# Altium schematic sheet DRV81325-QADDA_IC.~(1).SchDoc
size 431 x 279 mm; Date: Not shown in title block; ApprovedBy: Not shown in title block; CheckedBy: Not shown in title block; Author: Not shown in title block; CompanyName: Not shown in title block; Engineer: Not shown in title block; Organization: Not shown in title block; Address1: Not shown in title block; Address2: Not shown in title block; Address3: Not shown in title block; Address4: Not shown in title block; DocumentNumber: 1; Revision: Use project parameter SCH_Rev; SheetNumber: 4; SheetTotal: 5; PageSetup: Record=PageOptions¦CenterHorizontal=True¦CenterVertical=True¦PrintScale=1.00¦XCorrection=1.00¦YCorrection=1.00¦PrintKind=0¦BorderSize=5000000¦LeftOffset=0¦BottomOffset=0¦Orientation=2¦PaperLength=1000¦PaperWidth=1000¦Scale=100¦PaperSource=15¦PrintQuality=600¦MediaType=1¦DitherType=10¦PaperKind=Letter¦PrintScaleMode=1
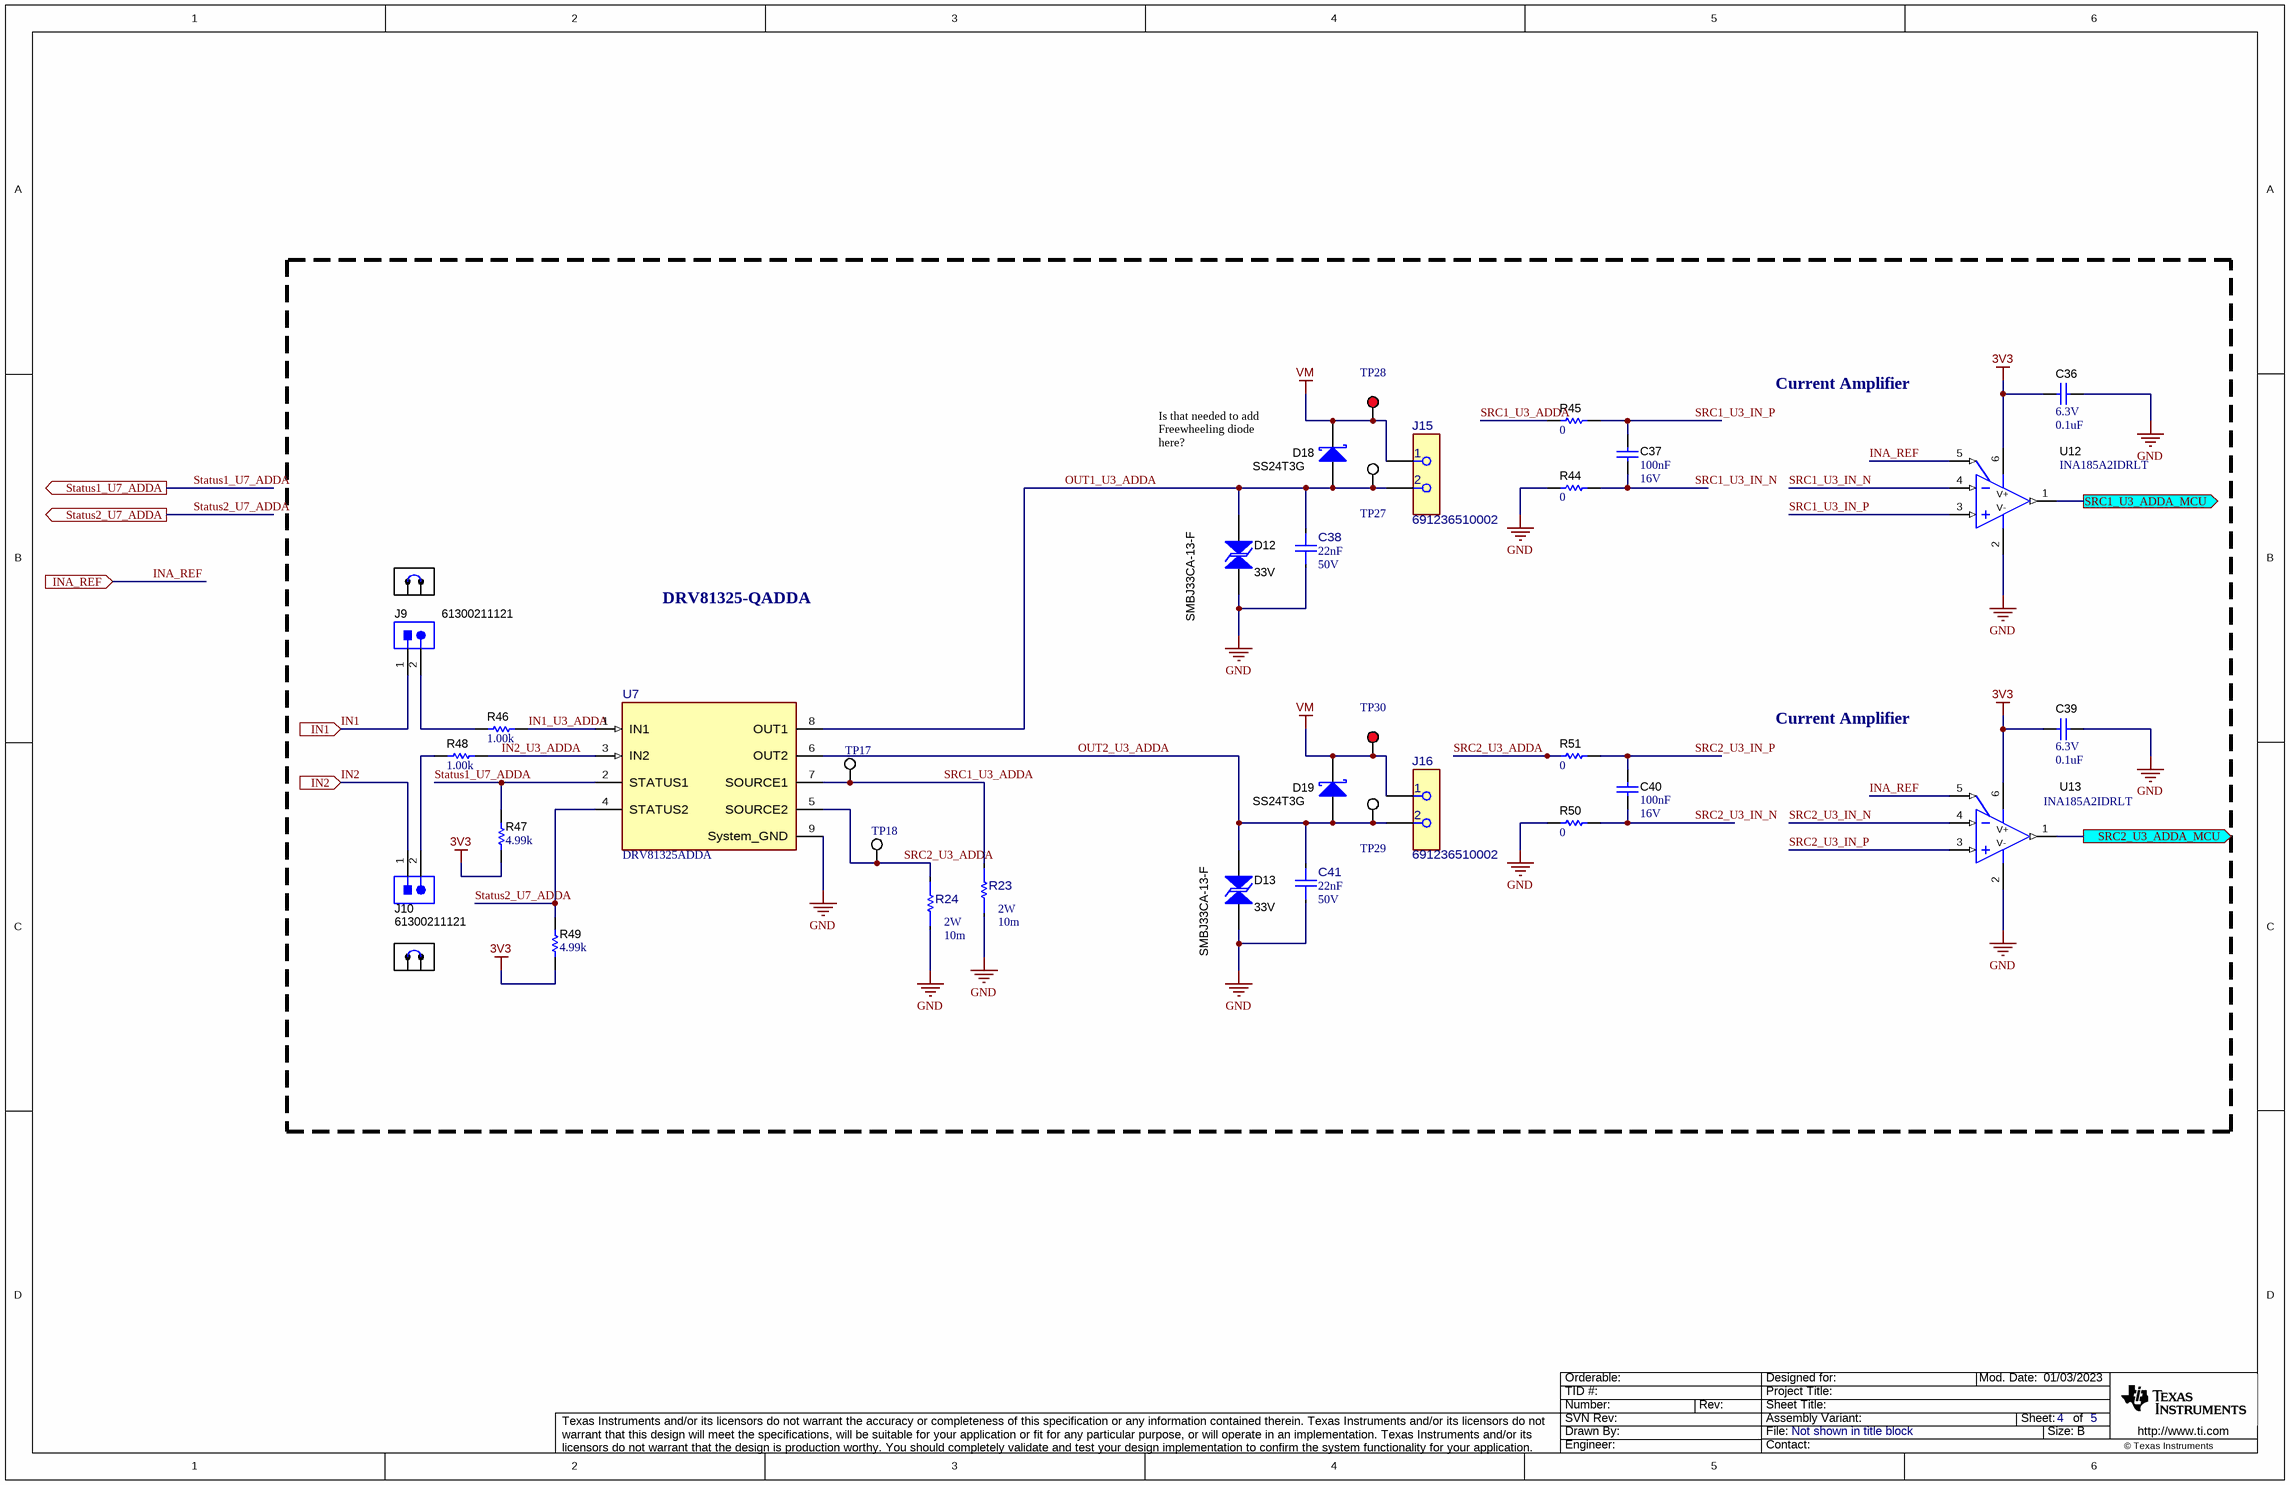
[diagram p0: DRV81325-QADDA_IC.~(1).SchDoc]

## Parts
C36  VDC_V: 6.3V  ValueDisplayed: 0.1uF  [0402]  (hidden comment: 885012105001)
C37  Cap_F: 100nF  VDC_V: 16V  [0603]  (hidden comment: 885012206046)
C38  Cap_F: 22nF  VDC_V: 50V  [FP-885012206091_0603-MFG]  (hidden comment: 885012206091)
C39  VDC_V: 6.3V  ValueDisplayed: 0.1uF  [0402]  (hidden comment: 885012105001)
C40  Cap_F: 100nF  VDC_V: 16V  [0603]  (hidden comment: 885012206046)
C41  Cap_F: 22nF  VDC_V: 50V  [FP-885012206091_0603-MFG]  (hidden comment: 885012206091)
D12  SMBJ33CA-13-F  value 33V  [SMB-Bi]
D13  SMBJ33CA-13-F  value 33V  [SMB-Bi]
D18  SS24T3G  [SMB]
D19  SS24T3G  [SMB]
J9  61300211121  [WURTH_61300211121]
J10  61300211121  [WURTH_61300211121]
J15  691236510002  [FP-691236510002_HHR2-MFG]
J16  691236510002  [FP-691236510002_HHR2-MFG]
R23  Res_ohm: 10m  Power_W: 2W  [FP-PCS2512DR0100ET_2512-MFG]  (hidden comment: PCS2512DR0100ET)
R24  Res_ohm: 10m  Power_W: 2W  [FP-PCS2512DR0100ET_2512-MFG]  (hidden comment: PCS2512DR0100ET)
R44  ValueDisplayed: 0  [0603]  (hidden comment: ERJ-3GEY0R00V)
R45  ValueDisplayed: 0  [0603]  (hidden comment: ERJ-3GEY0R00V)
R46  ValueDisplayed: 1.00k  [0603]  (hidden comment: RC0603FR-071KL)
R47  ValueDisplayed: 4.99k  [0603]  (hidden comment: RC0603FR-074K99L)
R48  ValueDisplayed: 1.00k  [0603]  (hidden comment: RC0603FR-071KL)
R49  ValueDisplayed: 4.99k  [0603]  (hidden comment: RC0603FR-074K99L)
R50  ValueDisplayed: 0  [0603]  (hidden comment: ERJ-3GEY0R00V)
R51  ValueDisplayed: 0  [0603]  (hidden comment: ERJ-3GEY0R00V)
SH-J9  60900213421  [Wurth_60900213421]  (value not drawn)
SH-J10  60900213421  [Wurth_60900213421]  (value not drawn)
TP17  5002  [Keystone5002]  (value not drawn)
TP18  5002  [Keystone5002]  (value not drawn)
TP27  5012  [Keystone5012]  (value not drawn)
TP28  5010  [Keystone5010]  (value not drawn)
TP29  5012  [Keystone5012]  (value not drawn)
TP30  5010  [Keystone5010]  (value not drawn)
U7  DRV81325ADDA  [DDA0008B-MFG]
U12  INA185A2IDRLT  [DRL0006A]
U13  INA185A2IDRLT  [DRL0006A]

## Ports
IN1 (in), IN2 (in), INA_REF (in), SRC1_U3_ADDA_MCU (out), SRC2_U3_ADDA_MCU (out), Status1_U7_ADDA (out), Status2_U7_ADDA (out)

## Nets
3V3: C36.2 C39.2 R47.1 R49.1 U12.6(V+) U13.6(V+)
GND: C36.1 C38.1 C39.1 C41.1 D12.1 D13.1 R23.1 R24.1 R44.1 R50.1 U7.9(System_GND) U12.2(V-) U13.2(V-)
VM: D18.1(K) D19.1(K) J15.1 J16.1 TP28.1 TP30.1
IN1: J9.1 ; port IN1
IN1_U3_ADDA: R46.2 U7.1(IN1)
IN2: J10.1 ; port IN2
IN2_U3_ADDA: R48.2 U7.3(IN2)
INA_REF: U12.5(REF) U13.5(REF) ; port INA_REF
OUT1_U3_ADDA: C38.2 D12.2 D18.2(A) J15.2 TP27.1 U7.8(OUT1)
OUT2_U3_ADDA: C41.2 D13.2 D19.2(A) J16.2 TP29.1 U7.6(OUT2)
SRC1_U3_ADDA: R23.2 R45.1 TP17.1 U7.7(SOURCE1)
SRC1_U3_ADDA_MCU: U12.1(OUT) ; port SRC1_U3_ADDA_MCU
SRC1_U3_IN_N: C37.2 R44.2 U12.4(IN-)
SRC1_U3_IN_P: C37.1 R45.2 U12.3(IN+)
SRC2_U3_ADDA: R24.2 R51.1 TP18.1 U7.5(SOURCE2)
SRC2_U3_ADDA_MCU: U13.1(OUT) ; port SRC2_U3_ADDA_MCU
SRC2_U3_IN_N: C40.2 R50.2 U13.4(IN-)
SRC2_U3_IN_P: C40.1 R51.2 U13.3(IN+)
Status1_U7_ADDA: R47.2 U7.2(STATUS1) ; port Status1_U7_ADDA
Status2_U7_ADDA: R49.2 U7.4(STATUS2) ; port Status2_U7_ADDA
NetJ9_2: J9.2 R46.1
NetJ10_2: J10.2 R48.1

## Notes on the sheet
- Current Amplifier
- Is that needed to add Freewheeling diode here?
- DRV81325-QADDA

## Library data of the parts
C36 C39 = CMP-0006219-2: CAP, CERM, 0.1 uF, 6.3 V, +/- 20%, X5R, 0402; Manufacturer: Wurth Elektronik; TaMin_C: -55°C; Polarized: N; SizeAreaWB_mm2: 3; Value1: Unknown; U/M: EA; Value: 0.1uF; TaMax_C: 85°C; SizeZ_mm: 0.6; SizeX_mm: 1; SizeY_mm: 0.5; Cap_F: 100nF; AEC Category: Q200
C37 C40 = CMP-0006829-4: CAP, CERM, 0.1 uF, 16 V, +/- 10%, X7R, 0603; Manufacturer: Wurth Elektronik; TaMin_C: -55°C; Polarized: N; SizeAreaWB_mm2: 4.68; Value1: Unknown; U/M: EA; Value: 0.1uF; TaMax_C: 125°C; SizeZ_mm: 1; SizeX_mm: 1.6; SizeY_mm: 0.8; SizeArea_mm2: 1.28; AEC Category: Q200
C38 C41 = CMP-0120895-1: 0.022 µF ±10% 50V Ceramic Capacitor X7R 0603 (1608 Metric); Manufacturer: Wurth Electronics; AEC Qualified: No; SizeZ_mm: 0.87mm; TempCo: 15%; Value: 22nF
D12 D13 = CMP-0005564-3: Diode, TVS, Bi, 33 V, SMB; Manufacturer: Diodes Inc.; SizeX_mm: 5.6; Ppk: 600W; SizeAreaWB_mm2: 44.156; SizeZ_mm: 2.6; SizeArea_mm2: 21.336; SizeY_mm: 3.81; AEC Category: Q101
D18 D19 = CMP-0028778-2: Diode, Schottky, 40 V, 2 A, AEC-Q101, SMB; Manufacturer: ON Semiconductor; AEC Qualified: Y; Value: 40V; TJmax_C: 150°C; Value1: 2A; Green_Lifecycle: Active; Value2: 0.5V; SizeX_mm: 5.6; SizeAreaWB_mm2: 44.156; SizeY_mm: 3.81; SizeArea_mm2: 21.336; Green_REACh: Passed; SizeZ_mm: 2.6; AEC Category: Q101; Vf_V: 500mV
J9 J10 = CMP-0054794-2: Header, 2.54 mm, 2x1, Gold, TH; Manufacturer: Wurth Elektronik; Shrouded: N; Gender: Male; Green_REACh: Passed; Pitch_mm: 2.54; Green_Lifecycle: Active; Row_Count: 1; Cert_UL: Y
J15 J16 = CMP-0121282-1: 2 Position Wire to Board Terminal Block Horizontal with Board 0.200" (5.08mm) Through Hole; Manufacturer: Wurth Electronics; Current_A: 20A; Row_Count: 1; Voltage_V: 300V; AEC Qualified: No; Conn Gender: Female; Is Female: yes; Max Wire Gauge: 12; Min Wire Gauge: 30; SizeZ_mm: 18.1mm
R23 R24 = CMP-0088493-1: 10 mOhms ±0.5% 2W Chip Resistor 2512 (6432 Metric) Automotive AEC-Q200, Current Sense, Moisture Resistant Metal Film; Manufacturer: Ohmite; SizeZ_mm: 0.664mm; AEC Grade: Grade 0; TempCo: 50ppm/°C; AEC Qualified: Yes; Tolerance_%: 0%
R44 R45 R50 R51 = CMP-0025874-4: RES, 0, 5%, 0.1 W, AEC-Q200 Grade 0, 0603; Manufacturer: Panasonic; Power_W: 100mW; TempCo: 600 ppm/C; Value_Code: 0000; Value: 0; EIA_Code: E24; SizeX_mm: 1.6; SizeY_mm: 0.8; SizeZ_mm: 1; Value2: 0.1W; SizeArea_mm2: 1.28; AEC Qualified: Y; VDC_V: 50V; AEC Category: Q200; SizeAreaWB_mm2: 4.68
R46 R48 = CMP-0022895-5: RES, 1.00 k, 1%, 0.1 W, 0603; Manufacturer: Yageo; Power_W: 100mW; TempCo: 100 ppm/C; Value_Code: 1k00; Value: 1.00k; EIA_Code: E96; Res_ohm: 1k; SizeX_mm: 1.6; SizeY_mm: 0.8; SizeZ_mm: 1; Value2: 0.1W; SizeArea_mm2: 1.28; AEC Qualified: N; VDC_V: 75V; AEC Category: Q200; SizeAreaWB_mm2: 4.68
R47 R49 = CMP-0023155-5: RES, 4.99 k, 1%, 0.1 W, 0603; Manufacturer: Yageo; Power_W: 100mW; TempCo: 100 ppm/C; Value_Code: 4k99; Value: 4.99k; EIA_Code: E96; SizeX_mm: 1.6; SizeY_mm: 0.8; SizeZ_mm: 1; Value2: 0.1W; SizeArea_mm2: 1.28; AEC Qualified: N; VDC_V: 75V; AEC Category: Q200; SizeAreaWB_mm2: 4.68
SH-J9 SH-J10 = CMP-0003761-2: Shunt, 2.54mm, Gold, Black; Manufacturer: Wurth Elektronik
TP17 TP18 = CMP-0055139-2: Test Point, Miniature, White, TH; Manufacturer: Keystone Electronics; ContactFinish: Silver; Green_REACh: Passed; CT: TRUE; Green_Lifecycle: Active; CNHeader: FALSE
TP27 TP29 = CMP-0055149-2: Test Point, Multipurpose, White, TH; Manufacturer: Keystone Electronics; ContactFinish: Silver; CT: TRUE; CNHeader: FALSE; Green_Lifecycle: Active; Green_REACh: Passed
TP28 TP30 = CMP-0055147-2: Test Point, Multipurpose, Red, TH; Manufacturer: Keystone Electronics; CT: TRUE; ContactFinish: Silver; Green_Lifecycle: Active; CNHeader: FALSE; Green_REACh: Passed
U7 = CMP-0127624-1: Dual Channel Protected Low side switch, HSOIC8; Manufacturer: Texas Instruments; SizeZ_mm: 1.7mm; AEC Qualified: Yes; AEC Grade: Grade 1; Max Supply Voltage: 5.5V; Min Supply Voltage: 3V; Number Of Outputs: 2; Standoff Height: 0mm; TaMax_C: +125°C; TaMin_C: -40°C; TJmax_C: +150°C
U12 U13 = CMP-0085241-1: Bidirectional, Precision Low- and High-Side Voltage Output, Current-Sense Amplifier, DRL0006A (SOT-5X3-6); Alternate Manufacturer: Texas Instruments; Alternate PartNumber: INA185A2IDRLR; SizeZ_mm: 0.6; CompType: IC; SizeY_mm: 1.6; SizeAreaWB_mm2: 6.76; AEC Qualified: N; SizeArea_mm2: 2.56; AEC Category: Q200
